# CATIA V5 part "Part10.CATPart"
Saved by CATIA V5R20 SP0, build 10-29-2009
Part number: tracé
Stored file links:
  C:\Users\Mike-7\Desktop\MMS_GR3\bfoltzer\CFAO_bfoltzer\Part10.CATPart
  C:\Users\Mike-7\Desktop\MMS_GR3\bfoltzer\CFAO_bfoltzer\sqlt_eolienne.CATProduct

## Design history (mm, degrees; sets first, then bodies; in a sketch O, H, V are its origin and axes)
Set1
  Point1: linked copy from another document
  Point2: linked copy from another document
  Line1: linked copy from another document
  Line2: linked copy from another document
  Point3: linked copy from another document
  Point4: linked copy from another document
  Line3: linked copy from another document
  Line4: linked copy from another document
  Point5: linked copy from another document
  Plane1 "Plan en contact avec bati": linked copy from another document
  Point6: linked copy from another document
  Point7: linked copy from another document
Body1 (main body)
  Sketch1 on Plane1, origin (480.7782, 0, 0), H (0, 1, 0), V (0, 0, 1)
    arc A1 centre (247.1063, 0) radius 110 from (347.5788, -44.7803) to (137.1063, 0) ccw
    point P1 (247.1063, 0)
    point P2 (347.5788, -44.7803)
    reference projected point E1 (247.1063, 0) from Point6
    reference projected point E2 (347.5788, -44.7803) from Point7
    coincidence: P1 E1, P2 E2
  LawDistProj1: Reference Sketch1.H, Definition Sketch1, LawScaling 1
  LawDistProj2: Reference Sketch1.H, Definition Sketch1, LawScaling 1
